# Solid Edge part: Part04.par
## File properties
Author: Robert a Rhodes jr
Template: Normal.par
Last saved by: Ashutosh-CADCIM
Revision: 6
Application: Solid Edge
Accuracy: 0.99
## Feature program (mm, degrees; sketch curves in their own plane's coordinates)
body "unnamed Body 1"
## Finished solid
Body 1: solid body, 43 faces, 102 edges, 68 vertices.
  Faces by surface: cylinder 28, plane 15
  Edges by curve: circle 56, line 46
Bounding box of the edges (mm): 1353.852 x 457.200 x 1295.400, from (-676.9261, -203.2, -533.4) to (676.9261, 254, 762).
Cylindrical faces by radius (mm): R50.8 x6, R95.25 x6, R127 x5, R152.4 x2, R254 x2, R431.8 x2, R508 x2, R533.4 x3
Planar faces by outward normal: +x 1, +y 7, -x 1, -y 2, oblique 4
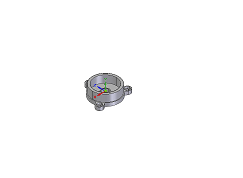
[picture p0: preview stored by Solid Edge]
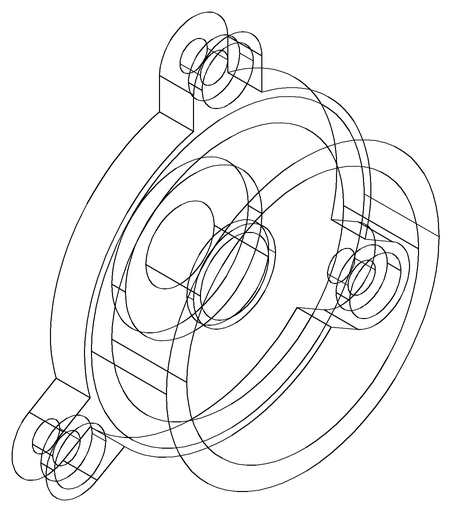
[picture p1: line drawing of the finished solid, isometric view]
